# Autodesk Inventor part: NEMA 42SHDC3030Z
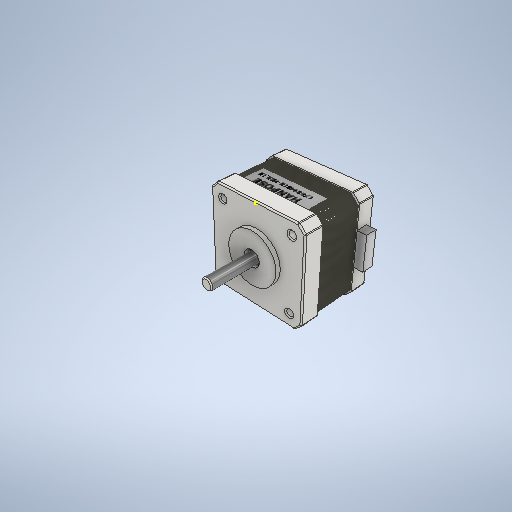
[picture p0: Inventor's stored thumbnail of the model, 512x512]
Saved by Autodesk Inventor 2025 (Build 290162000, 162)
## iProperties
GlobalPropertyList: <PropertyList/>
Created: 2012-11
Part Number: NEMA 42SHDC3030Z
Material: Alluminio 6061
Document SubType Name: Modeling
Designer: Romolicz Péter
Density: 2.7 g/cm^3
Mass: 153.938 g
Surface Area: 130.595 cm^2
Volume: 57.0142 cm^3
Appearance: Acciaio
d0: 7.000 mm
d1: 22.000 mm
d4: 5.000 mm
d5: 31.000 mm
d6: 31.000 mm
d9: 3.000 mm
d10: 3.000 mm
d11: 3.000 mm
d12: 3.000 mm
d39: 42.000 mm
d40: 42.000 mm
d41: 135.00 deg
d42: 55.154 mm
d43: 55.154 mm
d44: 27.577 mm
d45: 27.577 mm
d46: 24.000 mm
d47: 0.00 deg
d48: 2.000 mm
d49: 0.00 deg
d50: 33,700 mm
d51: 0.00 deg
d60: -8,000 mm
d126: 18,000 mm
d127: 0.00 deg
d128: 1.000 mm
d129: 1.000 mm
d130: 1.000 mm
d131: 1.000 mm
d132: 0.500 mm
d134: 0.500 mm
d135: 0.500 mm
d136: 0.500 mm
d137: 0.500 mm
d138: 1.000 mm
d139: 1.000 mm
d140: 0.500 mm
d141: 0.00 deg
d145: 0.125 mm
d148: 45,000 su
d150: 0.500 mm
d187: 40,000 mm
d188: 0.00 deg
d189: 47.000 mm
d190: 0.00 deg
d191: 0,600 mm
d192: 1.000 mm
d193: 0.500 mm
d196: 0.500 mm
d197: 1.200 mm
d198: 4.000 ul
d200: 1.200 mm
d205: 2.500 mm
d206: 2.500 mm
d207: 1.000 mm
d208: 0.00 deg
d209: 0.300 mm
d210: 10.000 mm
d211: 0.00 deg
d212: 10.000 mm
d213: 0.00 deg
d214: 10.000 mm
d215: 0.00 deg
d216: 10.000 mm
d217: 0.00 deg
d218: 0.200 mm
d219: 5.000 mm
d220: 0.00 deg
d221: 0.00 deg
Author: Romolicz Péter
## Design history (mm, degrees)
sketch "Sketch1"
  geometry: L1 (-15.5, 15.5)-(15.5, 15.5); L2 (15.5, 15.5)-(15.5, -15.5); L3 (15.5, -15.5)-(-15.5, -15.5); L4 (-15.5, -15.5)-(-15.5, 15.5); L5 (-21, 21)-(21, 21); L6 (21, 21)-(21, -21); L7 (21, -21)-(-21, -21); L8 (-21, -21)-(-21, 21); L9 (-21, 18)-(-18, 21); L10 (21, 18)-(18, 21); L11 (-21, -18)-(-18, -21); L12 (21, -18)-(18, -21); L13 (-21, 18)-(-21, -18); L14 (-18, -21)-(18, -21); L15 (21, -18)-(21, 18); L16 (18, 21)-(-18, 21); C1 r 3.5 at (0, 0); C2 r 11 at (0, 0); C3 r 2.5 at (0, 0); C4 r 1.5 at (-15.5, 15.5); C5 r 1.5 at (15.5, 15.5); C6 r 1.5 at (-15.5, -15.5); C7 r 1.5 at (15.5, -15.5); 5 further points
  constraints: 32 end point, 8 point on line, 7 centre point, 6 coincident, 5 parallel, 4 collinear, 4 midpoint, 4 perpendicular, 2 horizontal, 2 horizontal alignment, 2 vertical alignment, 1 concentric
  dimensions: "d0" = 7 diameter of C1; "d1" = 22 diameter of C2; "d4" = 5 diameter of C3; "d5" = 31 distance of L2.end L3.end; "d6" = 31 distance of L1.end L2.end; "d9" = 3 diameter of C4; "d10" = 3 diameter of C5; "d11" = 3 diameter of C6; "d12" = 3 diameter of C7; "d39" = 42 distance of L6.end L7.end; "d40" = 42 distance of L5.end L6.end; "d41" = 135 deg angle of L10 L6; "d42" = 55.154 distance between parallel lines of L10 L11 (derived); "d43" = 55.154 distance between parallel lines of L12 L9; "d44" = 27.577 distance from line of point (0, 0) L10 (derived); "d45" = 27.577 distance from line of point (0, 0) L12 (derived)
extrude "Extrusion1" new body sketch "Sketch1" distance "d46" = 24; taper "d47" = 0 deg; dims "d187" = 40, angle "d188" = 0 deg
extrude "Extrusion2" join sketch "Sketch1" distance "d48" = 2; taper "d49" = 0 deg
extrude "Extrusion3" join sketch "Sketch1" distance "d50" = 33.7; taper "d51" = 0 deg
workplane "Work Plane2"
sketch "Sketch4"
  geometry: L1 (-21, 18)-(-18, 21) reference; L2 (-21, 18)-(-18, 21) reference; L3 (-21, -18)-(-21, 18) reference; L4 (-18, -21)-(-21, -18) reference; L5 (18, -21)-(-18, -21) reference; L6 (21, -18)-(18, -21) reference; L7 (21, 18)-(21, -18) reference; L8 (18, 21)-(21, 18) reference; L9 (-18, 21)-(18, 21) reference; C1 r 1.5 at (-15.5, 15.5) reference; C2 r 1.5 at (-15.5, -15.5) reference; C3 r 1.5 at (15.5, 15.5) reference; C4 r 1.5 at (15.5, -15.5) reference; C5 r 11 at (0, 0) reference; 1 further point
extrude "Extrusion7" cut sketch "Sketch4" distance "d126" = 18; taper "d127" = 0 deg
sketch "Sketch5"
  geometry: L1 (-21, -18)-(-21, 18) reference; L2 (-18, -21)-(-21, -18) reference; L3 (18, -21)-(-18, -21) reference; L4 (21, -18)-(18, -21) reference; L5 (21, 18)-(21, -18) reference; L6 (18, 21)-(21, 18) reference; L7 (-18, 21)-(18, 21) reference; L8 (-21, 18)-(-18, 21) reference; L9 (-17.086, 20.5)-(-20.5, 17.086); L10 (-20.5, -17.086)-(-17.086, -20.5); L11 (-18, -21)-(-21, -18) reference; L12 (21, -18)-(18, -21) reference; L13 (18, 21)-(21, 18) reference; L14 (-21, 18)-(-18, 21) reference; L15 (20.5, -17.086)-(20.5, 17.086); L16 (17.086, 20.5)-(-17.086, 20.5); L17 (-20.5, 17.086)-(-20.5, -17.086); L18 (-17.086, -20.5)-(17.086, -20.5); L19 (17.086, -20.5)-(20.5, -17.086); L20 (20.5, 17.086)-(17.086, 20.5); C1 r 11 at (0, 0) reference; C2 r 1.5 at (15.5, -15.5) reference; C3 r 1.5 at (15.5, 15.5) reference; C4 r 1.5 at (-15.5, -15.5) reference; C5 r 1.5 at (-15.5, 15.5) reference
  constraints: 16 end point, 5 parallel
  dimensions: "d128" = 1 distance between parallel lines of L10 L2; "d131" = 1 distance between parallel lines of L8 L9; "d132" = 0.5 distance between parallel lines of L1 L17; "d134" = 0.5 distance between parallel lines of L5 L15; "d135" = 0.5 distance between parallel lines of L7 L16; "d137" = 0.5 distance between parallel lines of L18 L3; "d138" = 1 distance between parallel lines of L4 L19; "d139" = 1 distance between parallel lines of L6 L20
extrude "Extrusion8" join sketch "Sketch5" distance "d140" = 0.5; taper "d141" = 0 deg
chamfer "Chamfer1" distance "d145" = 0.125; stored, may be unused: second distance "d146" = 2, angle "d147" = 45 deg
extrude "Extrusion9" join sketch "Sketch1" distance "d189" = 47; taper "d190" = 0 deg
fillet "Fillet1" dims "d191" = 0.6
fillet "Fillet2" dims "d192" = 1
chamfer "Chamfer2" distance "d193" = 0.5; stored, may be unused: second distance "d194" = 2, angle "d195" = 45 deg
fillet "Fillet3" dims "d196" = 0.5
sketch "Sketch6" dims "d205" = 2.5
  geometry: L1 (35.502, 0)-(0, 0) reference; L2 (35.502, -7.1)-(0, -7.1) reference; C1 r 0.6 at (15.951, -2.5); C2 r 0.6 at (19.551, -2.5); 6 further points; 2 other entities
  constraints: 4 horizontal, 2 centre point, 2 horizontal alignment, 1 coincident, 1 midpoint, 1 vertical alignment, 13 other
  dimensions: "d197" = 1.2 diameter of C1; "d200" = 1.2 distance of C1.centre point (17.151, -2.5); "d206" = 2.5 distance from line of L1 point (17.751, -2.5)
  node "Schizzo - Serie rettangolare1" dims "d200" = 1.2, "d203" = 10
extrude "Extrusion10" join sketch "Sketch6" distance "d207" = 1; taper "d208" = 0 deg
fillet "Fillet4" dims "d209" = 0.3
extrude "Extrusion11" join sketch "Sketch6" distance "d210" = 10; taper "d211" = 0 deg
extrude "Extrusion12" join sketch "Sketch6" distance "d212" = 10; taper "d213" = 0 deg
extrude "Extrusion13" join sketch "Sketch6" distance "d214" = 10; taper "d215" = 0 deg
extrude "Extrusion14" join sketch "Sketch6" distance "d216" = 10; taper "d217" = 0 deg
extrude "Extrusion15" join sketch "Sketch6" distance "d218" = 0.2; taper "d220" = 0 deg; dims "d219" = 5, angle "d221" = 0 deg
sketch "Sketch11"
  geometry: L1 (20.5, 17.793)-(17.793, 20.5); L2 (20.5, 17.793)-(17.793, 20.5); L3 (2.875, 14)-(2.875, 17.769); L4 (2.875, 14)-(2.875, 17.769); L5 (-17.793, -20.5)-(17.793, -20.5); L6 (-20.5, -17.793)-(-17.793, -20.5); L7 (-20.5, -17.793)-(-17.793, -20.5); L8 (-21, 21)-(21, -21); L9 (21, 21)-(-21, -21); L10 (-2.646, 3)-(2.646, 3); L11 (2.646, 3)-(-2.646, 3); L12 (17.793, -20.5)-(20.5, -17.793); L13 (17.793, -20.5)-(20.5, -17.793); L14 (0, 15.181)-(1.023, 14.59); L15 (1.023, 14.59)-(1.023, 13.41); L16 (1.023, 13.41)-(0, 12.819); L17 (-1.022, 14.59)-(0, 15.181); L18 (-1.022, 13.41)-(-1.022, 14.59); L19 (-1.022, 13.41)-(0, 12.819); L20 (0, 12.819)-(-1.022, 13.41); L21 (-2.875, 14)-(-2.875, 17.769); L22 (-14.022, 15.5)-(-14.761, 14.22); L23 (-14.761, 16.78)-(-14.022, 15.5); L24 (-14.761, 14.22)-(-16.239, 14.22); L25 (-16.239, 16.78)-(-14.761, 16.78); L26 (-16.978, 15.5)-(-16.239, 14.22); L27 (-16.239, 14.22)-(-16.978, 15.5); L28 (-16.978, 15.5)-(-16.239, 16.78); L29 (-18.293, 49.829)-(-21, 47.122); L30 (-21, 47.122)-(-47.122, 21); L31 (-14, 2.875)-(-17.769, 2.875); L32 (-14, 2.875)-(-17.769, 2.875); L33 (-13.41, 1.023)-(-12.819, 0); L34 (-13.41, -1.022)-(-14.59, -1.022); L35 (-13.41, -1.022)-(-12.819, 0); L36 (-12.819, 0)-(-13.41, -1.022); L37 (-14.59, 1.023)-(-13.41, 1.023); L38 (-15.181, 0)-(-14.59, 1.023); L39 (-14.59, -1.022)-(-15.181, 0); L40 (-14, -2.875)-(-17.769, -2.875); L41 (-15.5, -14.022)-(-14.22, -14.761); L42 (-16.78, -14.761)-(-15.5, -14.022); L43 (-14.22, -14.761)-(-14.22, -16.239); L44 (-15.5, -16.978)-(-14.22, -16.239); L45 (-14.22, -16.239)-(-15.5, -16.978); L46 (-15.5, -16.978)-(-16.78, -16.239); L47 (-16.78, -16.239)-(-16.78, -14.761); L48 (-2.875, -14)-(-2.875, -17.769); L49 (-2.875, -14)-(-2.875, -17.769); L50 (-1.023, -13.41)-(0, -12.819); L51 (1.022, -13.41)-(1.022, -14.59); L52 (1.022, -13.41)-(0, -12.819); L53 (0, -12.819)-(1.022, -13.41); L54 (-1.023, -14.59)-(-1.023, -13.41); L55 (0, -15.181)-(-1.023, -14.59); L56 (1.022, -14.59)-(0, -15.181); L57 (2.875, -14)-(2.875, -17.769); L58 (14.022, -15.5)-(14.761, -14.22); L59 (14.761, -16.78)-(14.022, -15.5); L60 (14.761, -14.22)-(16.239, -14.22); L61 (16.978, -15.5)-(16.239, -14.22); L62 (16.239, -14.22)-(16.978, -15.5); L63 (16.978, -15.5)-(16.239, -16.78); L64 (16.239, -16.78)-(14.761, -16.78)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; C1 r 11 at (0, 0); C2 r 4 at (0, 0); C3 r 1.84 at (0, 14); C4 r 2.34 at (0, 14); C5 r 2.34 at (0, 14); C6 r 1.5 at (-9.899, 9.899); C7 r 1.5 at (-9.899, 9.899); C8 r 2.34 at (-15.5, 15.5); C9 r 2.875 at (-15.5, 15.5); C10 r 1.84 at (-14, 0); C11 r 2.34 at (-14, 0); C12 r 2.34 at (-14, 0); C13 r 1.5 at (-9.899, -9.899); C14 r 2.34 at (-15.5, -15.5); C15 r 2.875 at (-15.5, -15.5); C16 r 1.84 at (0, -14); C17 r 2.34 at (0, -14); C18 r 2.34 at (0, -14); C19 r 1.5 at (9.899, -9.899); C20 r 2.34 at (15.5, -15.5); C21 r 2.875 at (15.5, -15.5); C22 r 1.84 at (14, 0); C23 r 2.34 at (14, 0); C24 r 2.34 at (14, 0); C25 r 1.5 at (9.899, 9.899); C26 r 2.34 at (15.5, 15.5); C27 r 2.875 at (15.5, 15.5); A1 r 4.5 centre (0, 0) between (3.139, 3.224) and (3.139, -3.224); A2 r 18 centre (0, 0) between (-2.875, 17.769) and (2.875, 17.769); A3 r 4 centre (0, 0) between (0.527, 3.965) and (0.554, 3.961); A4 r 2.875 centre (0, 14) between (-2.875, 14) and (2.875, 14); A5 r 2.875 centre (0, 14) between (-2.875, 14) and (2.875, 14); A6 r 2.875 centre (-14, 0) between (-14, -2.875) and (-14, 2.875); A7 r 2.875 centre (-14, 0) between (-14, -2.875) and (-14, 2.875); A8 r 2.875 centre (0, -14) between (2.875, -14) and (-2.875, -14); A9 r 2.875 centre (0, -14) between (2.875, -14) and (-2.875, -14); A10 r 2.875 centre (14, 0) between (14, 2.875) and (14, -2.875); A11 r 2.875 centre (14, 0) between (14, 2.875) and (14, -2.875); 32 further points; 4 other entities
  constraints: 162 end point, 38 centre point, 25 coincident, 13 point on circle, 4 collinear, 3 midpoint, 2 horizontal, 1 concentric, 1 perpendicular, 1 tangent, 1 vertical, 257 other
  dimensions: "d239" = 42 distance of L8.end L9.end; "d240" = 42 distance of L9.end L8.start; "d241" = 36 diameter of A2; "d242" = 22 diameter of C1; "d245" = 360 deg dimension on A1.centre L3.end (derived)
  node "Schizzo - Serie circolare1" dims "d245" = 360 deg (derived)
extrude "Extrusion16" join sketch "Sketch11" distance "d247" = 5; taper "d248" = 0 deg
extrude "Extrusion17" join sketch "Sketch11" stored distance "d249" = 24; taper "d250" = 0 deg
extrude "Extrusion18" cut sketch "Sketch11" stored distance "d251" = 6; taper "d252" = 0 deg
extrude "Extrusion19" cut sketch "Sketch11" stored distance "d253" = 3; taper "d254" = 0 deg
extrude "Extrusion20" join sketch "Sketch11" stored distance "d255" = 3; taper "d256" = 0 deg
extrude "Extrusion21" cut sketch "Sketch11" stored distance "d257" = 1.8; taper "d258" = 0 deg
extrude "Extrusion22" cut sketch "Sketch11" distance "d259" = 5; taper "d260" = 0 deg
extrude "Extrusion23" join sketch "Sketch11" distance "d261" = 5; taper "d262" = 0 deg
extrude "Extrusion24" cut sketch "Sketch11" stored distance "d263" = 1.5; taper "d264" = 0 deg
extrude "Extrusion25" join sketch "Sketch11" stored distance "d265" = 2; taper "d266" = 0 deg
extrude "Extrusion26" join sketch "Sketch11" stored distance "d267" = 3; taper "d268" = 0 deg
extrude "Extrusion27" join sketch "Sketch11" stored distance "d269" = 15; taper "d270" = 0 deg
fillet "Fillet5" dims "d271" = 0.5
fillet "Fillet6" dims "d272" = 0.3
fillet "Fillet7" dims "d273" = 0.5
chamfer "Chamfer3" distance "d274" = 0.4; stored, may be unused: second distance "d275" = 2, angle "d276" = 45 deg
chamfer "Chamfer4" distance "d277" = 0.4; stored, may be unused: second distance "d278" = 2, angle "d279" = 45 deg
chamfer "Chamfer5" distance "d280" = 0.4; stored, may be unused: second distance "d281" = 2, angle "d282" = 45 deg
sketch "Sketch12"
  geometry: L1 (3.929, -0.75)-(6.442, -0.75); L2 (5.481, -2.833)-(6.648, -1.142); L3 (6.648, -1.142)-(5.481, -2.833); L4 (3.837, -2.941)-(5.275, -2.941); L5 (5.275, -2.941)-(3.837, -2.941); L6 (0, 0)-(-1.45, 0); L7 (3.929, 0.75)-(6.442, 0.75); L8 (5.481, 2.833)-(6.648, 1.142); L9 (6.648, 1.142)-(5.481, 2.833); L10 (3.837, 2.941)-(5.275, 2.941); L11 (5.275, 2.941)-(3.837, 2.941); C1 r 0.8 at (4.837, -1.845); C2 r 0.8 at (4.837, -1.845); C3 r 4 at (0, 0); C4 r 0.8 at (4.837, 1.845); C5 r 0.8 at (4.837, 1.845); C6 r 0.8 at (4.837, 1.845); C7 r 0.8 at (4.837, 1.845); A1 r 0.25 centre (6.442, -1) between (6.648, -1.142) and (6.442, -0.75); A2 r 0.25 centre (6.442, -1) between (6.648, -1.142) and (6.442, -0.75); A3 r 0.25 centre (5.275, -2.691) between (5.275, -2.941) and (5.481, -2.833); A4 r 0.25 centre (5.275, -2.691) between (5.275, -2.941) and (5.481, -2.833); A5 r 4.5 centre (0, 0) between (3.139, 3.224) and (3.139, -3.224); A6 r 1 centre (3.837, -3.941) between (3.837, -2.941) and (3.139, -3.224); A7 r 1 centre (3.837, -3.941) between (3.837, -2.941) and (3.139, -3.224); A8 r 4 centre (0, 0) between (3.929, -0.75) and (3.929, 0.75); A9 r 1 centre (3.837, 3.941) between (3.139, 3.224) and (3.837, 2.941); A10 r 0.25 centre (6.442, 1) between (6.442, 0.75) and (6.648, 1.142); A11 r 0.25 centre (6.442, 1) between (6.442, 0.75) and (6.648, 1.142); A12 r 0.25 centre (5.275, 2.691) between (5.481, 2.833) and (5.275, 2.941); A13 r 0.25 centre (5.275, 2.691) between (5.481, 2.833) and (5.275, 2.941); 3 further points
  constraints: 27 point on circle, 22 end point, 20 centre point, 13 symmetric about line, 5 coincident, 2 collinear, 1 horizontal, 1 parallel, 7 other
extrude "Extrusion28" join sketch "Sketch12" distance "d283" = 1; taper "d284" = 0 deg
sketch "Sketch13"
  geometry: L1 (-18, 5.4)-(-18, 28.6) reference; L2 (-18, 5.4)-(-18, 21.4); L3 (-18, 21.4)-(-17.646, 21.754); L4 (-17.646, 21.754)-(-18, 22.107); L5 (-18, 21.4)-(-18, 22.107); L6 (0, -6.4)-(0, 38.4) reference; L7 (-18, 5.4)-(18, 5.4) reference; 1 further point
  constraints: 8 end point, 4 point on line, 1 collinear, 1 perpendicular
  dimensions: "d285" = 16 distance of L2.start L2.end; "d286" = 0.5 distance of L2.end L3.end; "d287" = 135 deg angle of L2 L3
revolve "Revolution1" sketch "Sketch13" stored, may be unused: angle "d288" = 90 deg
chamfer "Chamfer6" distance "d289" = 0.4; stored, may be unused: second distance "d290" = 2, angle "d291" = 45 deg
chamfer "Smusso7" distance "d312" = 3; stored, may be unused: second distance "d313" = 2, angle "d314" = 45 deg
sketch "Schizzo14"
  geometry: L1 (2.646, -3)-(-2.646, -3); C1 r 2 at (0, 0) reference; A1 r 4 centre (0, 0) between (2.646, -3) and (-2.646, -3); 1 further point
  constraints: 2 end point, 2 point on circle, 1 centre point, 1 coincident, 1 horizontal
  dimensions: "d315" = 8 diameter of A1; "d316" = 3 distance from line of point (0, 0) L1
extrude "Estrusione29" cut sketch "Schizzo14" distance "d317" = 16; taper "d318" = 0 deg
fillet "Raccordo8" dims "d319" = 0.6
node "Piano di lavoro3"
sketch "Schizzo15"
  geometry: L1 (0.666, 7.875)-(34.837, 7.875) reference; L2 (3.264, 19)-(32.31, 19); L3 (32.31, 19)-(32.31, 7.875); L4 (32.31, 7.875)-(3.264, 7.875); L5 (3.264, 7.875)-(3.264, 19); 2 further points
  constraints: 8 end point, 2 parallel, 1 horizontal, 1 perpendicular, 1 point on line
extrude "Estrusione30" join sketch "Schizzo15" distance "d321" = 0.6; taper "d322" = 0 deg
sketch "Schizzo16"
  geometry: L1 (-10.946, 17.386)-(48.085, 17.386); L2 (48.085, 17.386)-(48.085, 2.528); L3 (48.085, 2.528)-(-10.946, 2.528); L4 (-10.946, 2.528)-(-10.946, 17.386); 1 further point
  constraints: 2 other
sketch "Schizzo17"
  geometry: L1 (0, 34.837)-(0, 0.666) reference; L2 (0, 25)-(-5, 25); L3 (-5, 25)-(-5, 10); L4 (-5, 10)-(0, 10); L5 (0, 10)-(0, 25); 2 further points
  constraints: 8 end point, 2 parallel, 1 horizontal, 1 perpendicular, 1 point on line
extrude "Estrusione31" new body sketch "Schizzo17" distance "d323" = 4; taper "d324" = 0 deg
sketch "Schizzo18"
  geometry: L1 (-1.5, 2)-(1.5, 2); A1 r 2.5 centre (0, 0) between (-1.5, 2) and (1.5, 2); 1 further point
  constraints: 2 end point, 2 point on circle, 1 centre point, 1 coincident, 1 horizontal
  dimensions: "d325" = 5 diameter of A1; "d326" = 2 distance from line of point (0, 0) L1
extrude "Estrusione32" cut sketch "Schizzo18" distance "d327" = 21; taper "d328" = 0 deg
sketch "Schizzo19"
  geometry: C1 r 2.5 at (0, 0) reference; C2 r 3.169 at (0, 0); 1 further point
  constraints: 1 centre point, 1 coincident
extrude "Estrusione33" cut sketch "Schizzo19" distance "d329" = 2; taper "d330" = 0 deg
sketch "Schizzo20"
  geometry: C1 r 2 at (0, 0) reference; C2 r 6.865 at (0, 0); 1 further point
  constraints: 1 centre point, 1 coincident
extrude "Estrusione34" cut sketch "Schizzo20" stored distance "d337" = 17; taper "d338" = 0 deg
chamfer "Smusso8" distance "d339" = 0.5; stored, may be unused: second distance "d340" = 2, angle "d341" = 45 deg
body "Solid1"
pattern_linear "Rectangular Pattern2" dims "d150" = 0.5
node "Projected Loop2"
node "Solido2"
other parameters: "d60" = -8, "d129" = 1, "d130" = 1, "d136" = 0.5, "d198" = 4, "d320" = -1
